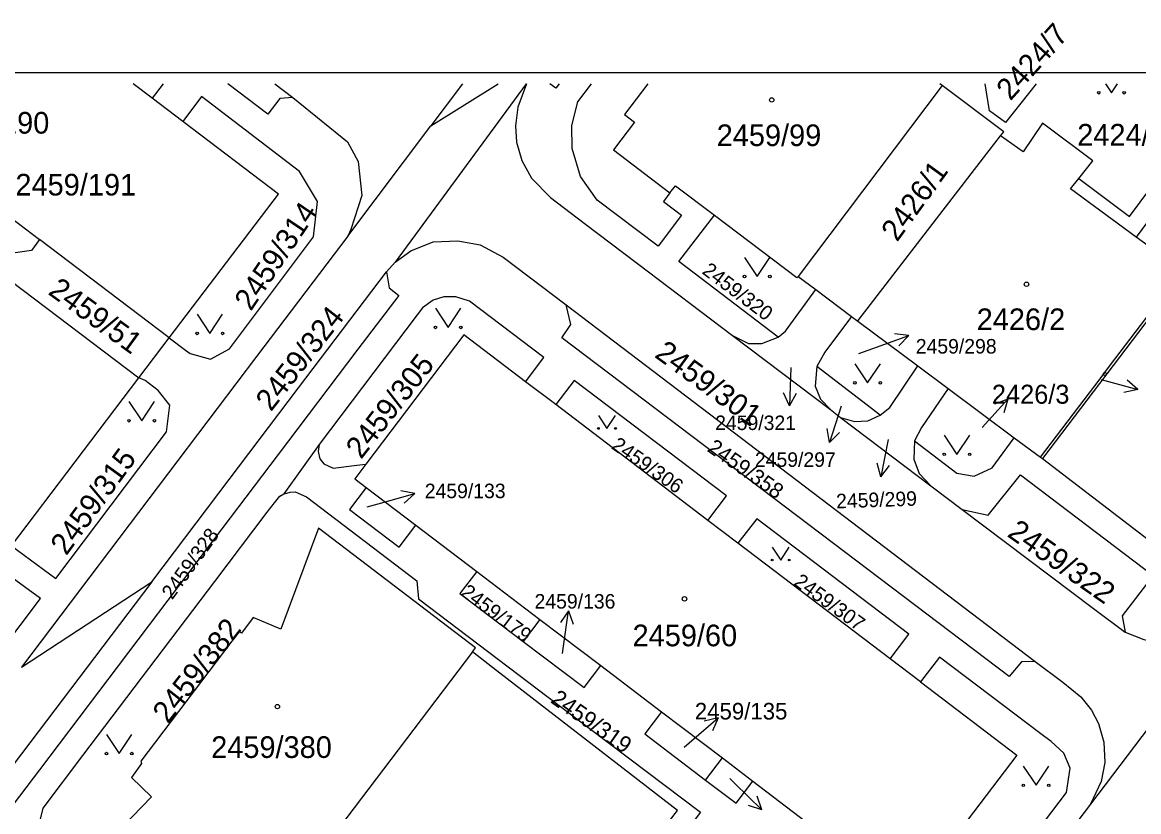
# Model space of a CAD drawing. Extents: x -606208 to -605570, y -1157873 to -1157573.
# Drawn here: x -605756.7 to -605669, y -1157634.5 to -1157572.5 of the extents above; entities that cross this region are included whole.
import ezdxf

# ---------------------------------------------------------------- set-up
doc = ezdxf.new("R2010")
doc.units = 0
doc.layers.add('Vrstva 1', color=7, linetype='Continuous')
doc.layers.add('Vrstva 62', color=7, linetype='Continuous')

msp = doc.modelspace()

# ---------------------------------------------------------------- linework, layer by layer
at = {"layer": 'Vrstva 1'}
msp.add_lwpolyline([(-606203.28, -1157873.46), (-605573.29, -1157873.46), (-605573.29, -1157576.47), (-606203.28, -1157576.47)], close=True, dxfattribs=at)
at = {"layer": 'Vrstva 62'}
for p, q in [((-605746.55, -1157578.47), (-605748.03, -1157577.34)), ((-605736.9, -1157577.34), (-605735.49, -1157578.42)), ((-605717.16, -1157577.34), (-605727.45, -1157591.35)), ((-605722.17, -1157577.34), (-605724.64, -1157580.63)), ((-605724.64, -1157580.63), (-605719.36, -1157577.34)), ((-605684.47, -1157577.48), (-605695.78, -1157592.46)), ((-605744.14, -1157580.3), (-605746.55, -1157578.47)), ((-605731.18, -1157589.31), (-605724.64, -1157580.63)), ((-605762.17, -1157584.44), (-605755.39, -1157589.57)), ((-605745.2, -1157597.29), (-605755.39, -1157589.57)), ((-605665.62, -1157592.02), (-605669.22, -1157589.38)), ((-605728.14, -1157592.1), (-605727.45, -1157591.35)), ((-605665.48, -1157592.12), (-605676.6, -1157606.77)), ((-605695.78, -1157592.46), (-605694.4, -1157593.5)), ((-605694.4, -1157593.5), (-605691.61, -1157595.6)), ((-605714.03, -1157594.7), (-605677.17, -1157622.7)), ((-605691.61, -1157595.6), (-605691.11, -1157595.98)), ((-605691.11, -1157595.98), (-605686.39, -1157599.49)), ((-605747.6, -1157600.44), (-605745.2, -1157597.29)), ((-605700.95, -1157597.1), (-605693.26, -1157602.92)), ((-605689.92, -1157598.12), (-605687.1, -1157597.094)), ((-605687.1, -1157597.094), (-605688.212, -1157596.966)), ((-605687.1, -1157597.094), (-605687.87, -1157597.907)), ((-605691.02, -1157598.53), (-605689.92, -1157598.12)), ((-605696.36, -1157599.63), (-605696.465, -1157602.629)), ((-605689.35, -1157603.35), (-605694.31, -1157599.55)), ((-605686.39, -1157599.49), (-605684.01, -1157601.27)), ((-605757.6, -1157613.62), (-605747.6, -1157600.44)), ((-605714.84, -1157602.53), (-605717.21, -1157600.73)), ((-605671.99, -1157600.57), (-605669.091, -1157601.347)), ((-605669.091, -1157601.347), (-605669.929, -1157600.604)), ((-605696.465, -1157602.629), (-605696.93, -1157601.611)), ((-605696.465, -1157602.629), (-605695.929, -1157601.646)), ((-605684.01, -1157601.27), (-605678.81, -1157605.13)), ((-605669.091, -1157601.347), (-605670.188, -1157601.571)), ((-605702.88, -1157611.62), (-605714.84, -1157602.53)), ((-605692.41, -1157602.66), (-605693.337, -1157605.514)), ((-605693.26, -1157602.92), (-605692.45, -1157603.54)), ((-605681.33, -1157604.33), (-605679.322, -1157602.1)), ((-605679.322, -1157602.1), (-605680.364, -1157602.509)), ((-605679.322, -1157602.1), (-605679.62, -1157603.179)), ((-605692.45, -1157603.54), (-605685.36, -1157608.92)), ((-605693.337, -1157605.514), (-605693.504, -1157604.407)), ((-605693.337, -1157605.514), (-605692.552, -1157604.716)), ((-605688.72, -1157605.26), (-605689.293, -1157608.206)), ((-605678.81, -1157605.13), (-605676.74, -1157606.66)), ((-605733.43, -1157605.67), (-605736.19, -1157609.53)), ((-605689.293, -1157608.206), (-605689.593, -1157607.127)), ((-605676.74, -1157606.66), (-605676.6, -1157606.77)), ((-605689.293, -1157608.206), (-605688.61, -1157607.318)), ((-605729.74, -1157609.03), (-605725.82, -1157612)), ((-605685.36, -1157608.92), (-605682.91, -1157610.77)), ((-605728.8, -1157610.33), (-605725.915, -1157609.503)), ((-605725.915, -1157609.503), (-605727.016, -1157609.298)), ((-605725.915, -1157609.503), (-605726.74, -1157610.26)), ((-605729.65, -1157610.57), (-605728.8, -1157610.33)), ((-605700.52, -1157613.42), (-605702.88, -1157611.62)), ((-605725.82, -1157612), (-605721.04, -1157615.63)), ((-605688.57, -1157622.49), (-605700.52, -1157613.42)), ((-605721.04, -1157615.63), (-605716.08, -1157619.4)), ((-605746.58, -1157616.44), (-605760.58, -1157634.9)), ((-605756.81, -1157623.15), (-605746.58, -1157616.44)), ((-605713.832, -1157618.718), (-605714.468, -1157619.64)), ((-605714.25, -1157621.69), (-605713.832, -1157618.718)), ((-605713.832, -1157618.718), (-605713.476, -1157619.78)), ((-605716.08, -1157619.4), (-605717.4, -1157621.13)), ((-605716.08, -1157619.4), (-605711.3, -1157623.03)), ((-605661.91, -1157619.51), (-605672.83, -1157633.91)), ((-605721.38, -1157621.96), (-605740.69, -1157647.37)), ((-605714.31, -1157622.09), (-605714.25, -1157621.69)), ((-605711.3, -1157623.03), (-605706.52, -1157626.66)), ((-605686.17, -1157624.31), (-605688.57, -1157622.49)), ((-605706.52, -1157626.66), (-605701.74, -1157630.28)), ((-605704.35, -1157629.09), (-605702.085, -1157627.121)), ((-605702.085, -1157627.121), (-605703.169, -1157627.4)), ((-605702.085, -1157627.121), (-605702.512, -1157628.156)), ((-605704.75, -1157629.44), (-605704.35, -1157629.09)), ((-605703.06, -1157632.02), (-605701.74, -1157630.28)), ((-605701.74, -1157630.28), (-605699.35, -1157632.1)), ((-605701.17, -1157631.9), (-605700.79, -1157632.26)), ((-605700.79, -1157632.26), (-605698.631, -1157634.345)), ((-605699.35, -1157632.1), (-605687.18, -1157641.34)), ((-605698.631, -1157634.345), (-605699.004, -1157633.289)), ((-605698.631, -1157634.345), (-605699.7, -1157634.009))]:
    msp.add_line(p, q, dxfattribs=at)
for points in [[(-605745.69, -1157577.34), (-605746.55, -1157578.47)], [(-605735.49, -1157578.42), (-605736.51, -1157578.49), (-605737.47, -1157579.73), (-605740.6, -1157577.34)], [(-605717.14, -1157577.34), (-605717.81, -1157579.18), (-605718.01, -1157580.64), (-605717.92, -1157581.93), (-605717.51, -1157583.37), (-605716.74, -1157584.75), (-605715.25, -1157586.26), (-605712.6, -1157588.27), (-605708.4, -1157591.45), (-605700.95, -1157597.1)], [(-605714.57, -1157577.34), (-605714.82, -1157577.68), (-605715.29, -1157577.34)], [(-605705.88, -1157585.89), (-605706.38, -1157586.59), (-605704.95, -1157587.66), (-605706.78, -1157590.09), (-605711.58, -1157586.47), (-605712.88, -1157584.63), (-605713.55, -1157582.42), (-605713.58, -1157580.6), (-605713.1, -1157578.76), (-605712.03, -1157577.34)], [(-605707.6, -1157577.34), (-605709.44, -1157579.75), (-605708.65, -1157580.35), (-605710.31, -1157582.53), (-605705.88, -1157585.89)], [(-605684.47, -1157577.48), (-605684.65, -1157577.34)], [(-605679.89, -1157581.42), (-605679.64, -1157581.1), (-605684.47, -1157577.48)], [(-605677.09, -1157577.34), (-605679.5, -1157580.37), (-605680.75, -1157579.46), (-605681.1, -1157577.34)], [(-605673.74, -1157584.77), (-605669.75, -1157587.77), (-605664.04, -1157580.08), (-605664.11, -1157578.97), (-605666.29, -1157577.34)], [(-605671.63, -1157577.34), (-605671.17, -1157578.04), (-605670.71, -1157577.34)], [(-605745.2, -1157597.29), (-605743.94, -1157598.25), (-605743.56, -1157598.53), (-605741.97, -1157598.97), (-605740.48, -1157598.15), (-605733.86, -1157589.35), (-605733.55, -1157586.57), (-605734.98, -1157584.22), (-605742.68, -1157578.34), (-605744.14, -1157580.3)], [(-605735.49, -1157578.42), (-605731.19, -1157581.9), (-605730.36, -1157583.45), (-605730.07, -1157586.12), (-605730.94, -1157588.77), (-605731.18, -1157589.31)], [(-605745.2, -1157597.29), (-605736.63, -1157586), (-605744.14, -1157580.3)], [(-605673.74, -1157584.77), (-605672.63, -1157583.39), (-605676.59, -1157580.43), (-605678.1, -1157582.67), (-605679.89, -1157581.42)], [(-605691.11, -1157595.98), (-605691.07, -1157595.92), (-605681.23, -1157583.15), (-605679.89, -1157581.42)], [(-605660.02, -1157584.93), (-605663.8, -1157582.06), (-605669.22, -1157589.38)], [(-605676.6, -1157606.77), (-605666.72, -1157614.32), (-605643.36, -1157583.54)], [(-605705.88, -1157585.89), (-605705.42, -1157585.35), (-605702.47, -1157587.58), (-605702.37, -1157587.65)], [(-605669.22, -1157589.38), (-605674.4, -1157585.58), (-605673.74, -1157584.77)], [(-605697.35, -1157597.24), (-605705.16, -1157591.3), (-605702.37, -1157587.65)], [(-605702.37, -1157587.65), (-605695.88, -1157592.56), (-605695.78, -1157592.46)], [(-605755.39, -1157589.57), (-605756.03, -1157590.43), (-605760.1, -1157591)], [(-605731.18, -1157589.31), (-605738.34, -1157598.75), (-605744.53, -1157606.92), (-605756.81, -1157623.15)], [(-605727.45, -1157591.35), (-605726.21, -1157590.46), (-605724.46, -1157589.75), (-605722.54, -1157589.66), (-605720.77, -1157589.99), (-605718.96, -1157590.95), (-605714.03, -1157594.7)], [(-605700.01, -1157590.969), (-605699.01, -1157592.47), (-605698.01, -1157590.969)], [(-605728.14, -1157592.1), (-605727.92, -1157593.36), (-605727.16, -1157593.95), (-605730.39, -1157598.18), (-605736.65, -1157606.46), (-605742.95, -1157614.78), (-605749.21, -1157623.05), (-605755.41, -1157631.22), (-605758.56, -1157635.36), (-605759.42, -1157634.71), (-605760.58, -1157634.9)], [(-605746.58, -1157616.44), (-605741.32, -1157609.49), (-605735.05, -1157601.22), (-605728.14, -1157592.1)], [(-605676.74, -1157606.66), (-605672.06, -1157600.5), (-605671.32, -1157599.52), (-605665.62, -1157592.02)], [(-605757.81, -1157593.07), (-605757.63, -1157592.83), (-605747.6, -1157600.44)], [(-605717.21, -1157600.73), (-605715.78, -1157598.82), (-605721.62, -1157594.42), (-605722.68, -1157594.06), (-605723.63, -1157594.07), (-605724.48, -1157594.34), (-605725.3, -1157594.93), (-605725.73, -1157595.48), (-605733.43, -1157605.67)], [(-605697.35, -1157597.24), (-605696.78, -1157596.76), (-605694.4, -1157593.5)], [(-605724.29, -1157594.969), (-605723.29, -1157596.47), (-605722.29, -1157594.969)], [(-605677.17, -1157622.7), (-605678.25, -1157622.74), (-605679.21, -1157623.89), (-605714.35, -1157597.28), (-605713.64, -1157596.23), (-605714.03, -1157594.7)], [(-605743.01, -1157595.439), (-605742.01, -1157596.94), (-605741.01, -1157595.439)], [(-605691.61, -1157595.6), (-605693.7, -1157598.42), (-605694.31, -1157599.55)], [(-605717.21, -1157600.73), (-605722.05, -1157597.06), (-605729.77, -1157607.21)], [(-605700.95, -1157597.1), (-605699.68, -1157597.74), (-605698.65, -1157597.73), (-605697.35, -1157597.24)], [(-605691.33, -1157599.319), (-605690.33, -1157600.82), (-605689.33, -1157599.319)], [(-605694.31, -1157599.55), (-605694.45, -1157601.08), (-605694.04, -1157602.11), (-605693.26, -1157602.92)], [(-605689.35, -1157603.35), (-605688.58, -1157602.77), (-605686.39, -1157599.49)], [(-605757.6, -1157613.62), (-605754.12, -1157616.18), (-605745.42, -1157604.68), (-605745.15, -1157602.58), (-605746.08, -1157601.43), (-605747.11, -1157600.65), (-605747.6, -1157600.44)], [(-605702.88, -1157611.62), (-605701.42, -1157609.7), (-605713.38, -1157600.63), (-605714.84, -1157602.53)], [(-605684.01, -1157601.27), (-605686.09, -1157604.32), (-605686.65, -1157605.37)], [(-605748.37, -1157602.299), (-605747.37, -1157603.8), (-605746.37, -1157602.299)], [(-605711.48, -1157603.394), (-605710.81, -1157604.4), (-605710.14, -1157603.394)], [(-605692.45, -1157603.54), (-605691.35, -1157603.87), (-605690.32, -1157603.8), (-605689.35, -1157603.35)], [(-605686.65, -1157605.37), (-605686.7, -1157606.82), (-605686.28, -1157607.93), (-605685.36, -1157608.92)], [(-605686.65, -1157605.37), (-605683.31, -1157607.92), (-605681.96, -1157608.16), (-605680.55, -1157607.5), (-605678.81, -1157605.13)], [(-605684.31, -1157604.939), (-605683.31, -1157606.44), (-605682.31, -1157604.939)], [(-605733.43, -1157605.67), (-605733.51, -1157606.22), (-605733.36, -1157606.78), (-605733.07, -1157607.18), (-605732.33, -1157607.53), (-605730.47, -1157607.29), (-605729.77, -1157607.21)], [(-605729.77, -1157607.21), (-605730.63, -1157608.35), (-605729.74, -1157609.03)], [(-605682.91, -1157610.77), (-605680.85, -1157611.22), (-605678.31, -1157608.04), (-605667.9, -1157615.94), (-605670.34, -1157619.11), (-605670.1, -1157620.41)], [(-605729.74, -1157609.03), (-605731.05, -1157610.76), (-605727.14, -1157613.73), (-605725.82, -1157612)], [(-605741.59, -1157648.49), (-605746.97, -1157644.39), (-605754.54, -1157638.66), (-605755.72, -1157636.71), (-605755.12, -1157634.23), (-605751.99, -1157630.1), (-605741.63, -1157616.42), (-605737.51, -1157610.98), (-605736.94, -1157610.24), (-605736.51, -1157609.73), (-605736.19, -1157609.53)], [(-605736.19, -1157609.53), (-605735.96, -1157609.49), (-605735.7, -1157609.4), (-605735.32, -1157609.39), (-605734.43, -1157609.77), (-605725.74, -1157616.38), (-605725.63, -1157617.79), (-605714.66, -1157626.08), (-605703.47, -1157634.55), (-605710.49, -1157643.82), (-605712.75, -1157646.8), (-605714.68, -1157645.32), (-605726.1, -1157660.28)], [(-605682.91, -1157610.77), (-605672.59, -1157618.54), (-605670.1, -1157620.41)], [(-605688.57, -1157622.49), (-605687.08, -1157620.56), (-605699.03, -1157611.51), (-605700.52, -1157613.42)], [(-605721.38, -1157621.96), (-605721.13, -1157621.62), (-605733.49, -1157612.23), (-605736.44, -1157620.16), (-605738.62, -1157619.25), (-605739.52, -1157620.49), (-605739.7, -1157620.36), (-605747.44, -1157630.54), (-605747.38, -1157630.72), (-605748.16, -1157631.81), (-605746.6, -1157633.34), (-605751.88, -1157638.81), (-605740.69, -1157647.37)], [(-605697.83, -1157613.734), (-605697.16, -1157614.74), (-605696.49, -1157613.734)], [(-605768.68, -1157628.21), (-605767.19, -1157629.12), (-605764.95, -1157629.39), (-605763.34, -1157628.36), (-605755.33, -1157617.77), (-605758.82, -1157615.23)], [(-605721.04, -1157615.63), (-605722.36, -1157617.36), (-605717.4, -1157621.13)], [(-605670.1, -1157620.41), (-605668.62, -1157620.98), (-605667.18, -1157621.28), (-605666.16, -1157621.2), (-605663.7, -1157620.59), (-605661.91, -1157619.51)], [(-605717.4, -1157621.13), (-605712.61, -1157624.76), (-605711.3, -1157623.03)], [(-605725.55, -1157658.46), (-605722.79, -1157654.79), (-605722.95, -1157654.71), (-605715.01, -1157644.22), (-605713.64, -1157645.23), (-605705.28, -1157634.41), (-605719.8, -1157623.18), (-605721.38, -1157621.96)], [(-605686.35, -1157640.24), (-605685.9, -1157642.45), (-605684.07, -1157643.47), (-605683.04, -1157643.33), (-605681.96, -1157642.56), (-605674.71, -1157633), (-605674.42, -1157631.08), (-605674.91, -1157629.9), (-605675.91, -1157628.98), (-605676.72, -1157628.38), (-605684.69, -1157622.37), (-605686.17, -1157624.31)], [(-605677.17, -1157622.7), (-605674.99, -1157624.33), (-605673.59, -1157625.48), (-605672.74, -1157626.53), (-605672.18, -1157627.58), (-605671.77, -1157629.03), (-605671.7, -1157630.63), (-605671.99, -1157632.14), (-605672.83, -1157633.91)], [(-605686.17, -1157624.31), (-605678.61, -1157630.05), (-605683.42, -1157636.39), (-605686.35, -1157640.24)], [(-605706.52, -1157626.66), (-605707.83, -1157628.39), (-605703.06, -1157632.02)], [(-605750.14, -1157628.439), (-605749.14, -1157629.94), (-605748.14, -1157628.439)], [(-605678.1, -1157630.929), (-605677.1, -1157632.43), (-605676.1, -1157630.929)], [(-605703.06, -1157632.02), (-605700.67, -1157633.83), (-605699.35, -1157632.1)], [(-605672.83, -1157633.91), (-605683.34, -1157647.76), (-605684.55, -1157647.87), (-605687.84, -1157645.41), (-605690.7, -1157649.16), (-605687.61, -1157651.55), (-605687.52, -1157653.02), (-605688.97, -1157653.43), (-605692.14, -1157651.06), (-605697.93, -1157658.7), (-605694.8, -1157661.08), (-605694.82, -1157662.59), (-605696.28, -1157663.07), (-605699.44, -1157660.68), (-605708.05, -1157672.09), (-605705.13, -1157674.27), (-605704.79, -1157676.02), (-605706.04, -1157677.6), (-605707.7, -1157678.63), (-605709.71, -1157679.22), (-605711.22, -1157679.22), (-605712.76, -1157678.96)]]:
    msp.add_lwpolyline(points, dxfattribs=at)
for centre, radius in [((-605672.17, -1157578.04), 0.1), ((-605670.17, -1157578.04), 0.1), ((-605697.864, -1157578.605), 0.175), ((-605700.01, -1157592.469), 0.1), ((-605698.01, -1157592.469), 0.1), ((-605677.847, -1157593.079), 0.175), ((-605724.29, -1157596.469), 0.1), ((-605722.29, -1157596.469), 0.1), ((-605743.01, -1157596.939), 0.1), ((-605741.01, -1157596.939), 0.1), ((-605671.695, -1157600.129), 0.117), ((-605691.33, -1157600.819), 0.1), ((-605689.33, -1157600.819), 0.1), ((-605748.37, -1157603.799), 0.1), ((-605746.37, -1157603.799), 0.1), ((-605711.48, -1157604.4), 0.067), ((-605710.14, -1157604.4), 0.067), ((-605684.31, -1157606.439), 0.1), ((-605682.31, -1157606.439), 0.1), ((-605697.83, -1157614.74), 0.067), ((-605696.49, -1157614.74), 0.067), ((-605704.717, -1157617.789), 0.175), ((-605736.707, -1157626.249), 0.175), ((-605750.14, -1157629.939), 0.1), ((-605748.14, -1157629.939), 0.1), ((-605678.1, -1157632.429), 0.1), ((-605676.1, -1157632.429), 0.1)]:
    msp.add_circle(centre, radius, dxfattribs=at)

# ---------------------------------------------------------------- texts
for s, height, rotation, p in [('2424/7', 1.7, 48, (-605679.11, -1157578.73)), ('2426/1', 1.7, 54, (-605688.015, -1157589.813)), ('2459/314', 1.7, 56, (-605738.79, -1157595.25)), ('2459/320', 1.139, 323, (-605703.408, -1157592.188)), ('2459/51', 1.7, 324, (-605754.8, -1157593.81)), ('2459/324', 1.7, 52, (-605737.21, -1157603.14)), ('2459/301', 1.7, 324, (-605707.15, -1157598.75)), ('2459/305', 1.7, 52, (-605730.13, -1157606.88)), ('2459/306', 1.139, 325, (-605710.54, -1157605.93)), ('2459/358', 1.209, 325, (-605703.01, -1157606.14)), ('2459/315', 1.7, 54, (-605753.29, -1157614.45)), ('2459/299', 1.139, 2, (-605692.787, -1157610.685)), ('2459/322', 1.7, 325, (-605679.44, -1157612.83)), ('2459/328', 1.139, 54, (-605744.97, -1157617.91)), ('2459/307', 1.139, 324, (-605696.21, -1157616.64)), ('2459/179', 1.139, 323, (-605722.37, -1157617.45)), ('2459/382', 1.7, 52, (-605745.31, -1157627.65)), ('2459/319', 1.284, 325, (-605715.32, -1157625.88))]:
    msp.add_text(s, height=height, rotation=rotation, dxfattribs=at).set_placement(p)
for s, height, p in [('2459/190', 1.7, (-605764.11, -1157581.25)), ('2459/99', 1.7, (-605702.19, -1157582.23)), ('2424/5', 1.7, (-605673.86, -1157582.19)), ('2459/191', 1.7, (-605757.29, -1157586.11)), ('2426/2', 1.7, (-605681.76, -1157596.68)), ('2459/298', 1.139, (-605686.549, -1157598.52)), ('2426/3', 1.49, (-605680.567, -1157602.46)), ('2459/321', 1.139, (-605702.312, -1157604.529)), ('2459/297', 1.139, (-605699.188, -1157607.419)), ('2459/133', 1.139, (-605725.13, -1157609.88)), ('2459/136', 1.139, (-605716.502, -1157618.55)), ('2459/60', 1.7, (-605708.8, -1157621.51)), ('2459/135', 1.304, (-605703.908, -1157627.26)), ('2459/380', 1.7, (-605741.91, -1157630.28))]:
    msp.add_text(s, height=height, dxfattribs=at).set_placement(p)

doc.saveas('drawing.dxf')
